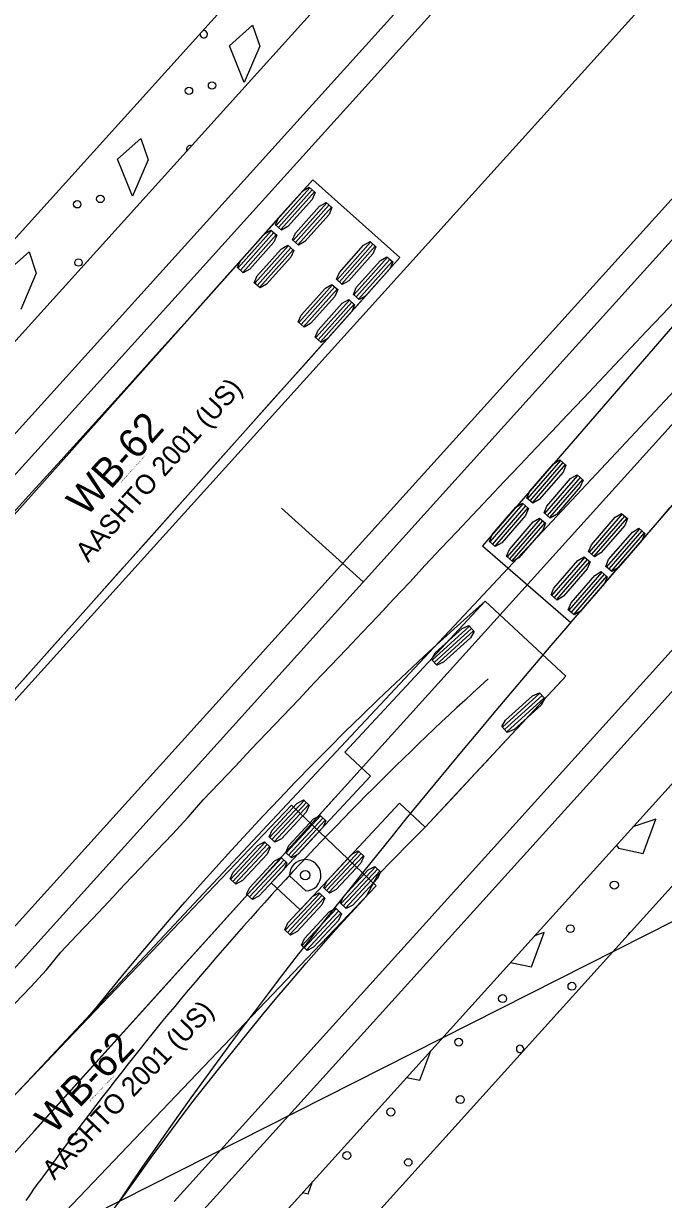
# Model space of a CAD drawing. Extents: x 1262642 to 1268358, y 767825 to 773481.
# Drawn here: x 1266867.8 to 1266914.3, y 772243.3 to 772328.8 of the extents above; entities that cross this region are included whole.
import ezdxf

# ---------------------------------------------------------------- set-up
doc = ezdxf.new("R2010")
doc.units = 0
for name, color, linetype in [('Prop Conc 2ft 6in Curb and Gutter', 7, 'Continuous'), ('Prop Conc 4in Sidewalk', 7, 'Continuous'), ('Prop Dimension Text', 7, 'Continuous'), ('Prop EOT', 7, 'Continuous'), ('Prop Horizontal Alignment', 7, 'Continuous'), ('Prop Horizontal Alignment Tick Large', 7, 'Continuous'), ('Prop Lane Lines', 7, 'Continuous'), ('Scratch_Level_3', 7, 'Continuous')]:
    doc.layers.add(name, color=color, linetype=linetype)

msp = doc.modelspace()

# ---------------------------------------------------------------- linework, layer by layer
at = {"layer": 'Prop Conc 2ft 6in Curb and Gutter'}
for p, q in [((1267131.944, 772606.254), (1266835.453, 772278.077)), ((1267135.454, 772602.68), (1266839.163, 772274.725)), ((1267138.613, 772599.464), (1266842.502, 772271.708)), ((1267174.15, 772567.197), (1266880.184, 772241.815)), ((1266883.523, 772238.798), (1267177.489, 772564.181)), ((1267181.289, 772560.929), (1266887.233, 772235.447)), ((1266882.725, 772327.166), (1266884.411, 772328.663)), ((1266884.411, 772328.663), (1266884.935, 772327.129)), ((1266883.805, 772324.487), (1266882.725, 772327.166)), ((1266884.935, 772327.129), (1266883.805, 772324.487)), ((1266874.601, 772318.921), (1266876.287, 772320.419)), ((1266876.287, 772320.419), (1266876.811, 772318.885)), ((1266875.682, 772316.242), (1266874.601, 772318.921)), ((1266876.811, 772318.885), (1266875.682, 772316.242)), ((1266866.478, 772310.677), (1266868.164, 772312.174)), ((1266868.164, 772312.174), (1266868.688, 772310.64)), ((1266868.688, 772310.64), (1266867.559, 772307.998)), ((1266913.737, 772270.958), (1266912.067, 772270.393)), ((1266912.818, 772268.458), (1266913.737, 772270.958)), ((1266910.864, 772269.061), (1266911.012, 772268.834)), ((1266911.012, 772268.834), (1266912.818, 772268.458)), ((1266904.695, 772260.214), (1266905.614, 772262.713)), ((1266905.614, 772262.713), (1266904.916, 772262.478)), ((1266903.159, 772260.533), (1266904.695, 772260.214)), ((1266896.572, 772251.97), (1266897.36, 772254.115)), ((1266895.604, 772252.171), (1266896.572, 772251.97)), ((1266888.449, 772243.725), (1266888.774, 772244.611)), ((1266888.049, 772243.808), (1266888.449, 772243.725))]:
    msp.add_line(p, q, dxfattribs=at)
for centre, radius in [((1266879.787, 772323.887), 0.268), ((1266881.464, 772324.276), 0.268), ((1266873.341, 772316.031), 0.268), ((1266871.664, 772315.642), 0.268), ((1266871.754, 772311.404), 0.268), ((1266910.712, 772266.151), 0.292), ((1266907.515, 772262.984), 0.285), ((1266907.633, 772258.804), 0.289), ((1266902.589, 772257.906), 0.292), ((1266899.392, 772254.74), 0.285), ((1266899.51, 772250.56), 0.289), ((1266894.466, 772249.662), 0.292), ((1266891.268, 772246.495), 0.285), ((1266895.732, 772246.001), 0.268)]:
    msp.add_circle(centre, radius, dxfattribs=at)
for centre, start, end in [((1266880.863, 772327.995), 168.70007, 107.10757), ((1266879.877, 772319.648), 68.58721, 207.22043), ((1266911.979, 772262.49), 108.17506, 167.63259), ((1266903.856, 772254.245), 112.12802, 313.44003), ((1266903.856, 772254.245), 322.36762, 112.12802)]:
    msp.add_arc(centre, 0.268, start, end, dxfattribs=at)
at = {"layer": 'Prop Conc 4in Sidewalk'}
for p, q in [((1267131.944, 772606.254), (1266835.453, 772278.077)), ((1267135.454, 772602.68), (1266839.163, 772274.725)), ((1267177.489, 772564.181), (1266883.523, 772238.798)), ((1267181.199, 772560.829), (1266887.233, 772235.447))]:
    msp.add_line(p, q, dxfattribs=at)
at = {"layer": 'Prop Dimension Text'}
msp.add_lwpolyline([(1266927.819, 772269.993), (1266826.047, 772218.568)], dxfattribs=at)
at = {"layer": 'Prop EOT'}
for p, q in [((1267140.017, 772598.035), (1266843.986, 772270.367)), ((1267172.665, 772568.538), (1266878.7, 772243.156))]:
    msp.add_line(p, q, dxfattribs=at)
at = {"layer": 'Prop Horizontal Alignment'}
msp.add_line((1266770.936, 772153.71), (1267443.049, 772897.651), dxfattribs=at)
msp.add_arc((1275047.307, 780021.225), 11400, 222.9935866, 225.4043192, dxfattribs=at)
at = {"layer": 'Prop Horizontal Alignment Tick Large'}
msp.add_line((1266892.443, 772288.202), (1266886.507, 772293.565), dxfattribs=at)
at = {"layer": 'Prop Lane Lines'}
for p, q in [((1267148.179, 772590.66), (1266852.149, 772262.993)), ((1267156.341, 772583.286), (1266860.311, 772255.619)), ((1267164.503, 772575.912), (1266868.473, 772248.245)), ((1266890.345, 772272.454), (1266862.92, 772242.098))]:
    msp.add_line(p, q, dxfattribs=at)
at = {"layer": 'Scratch_Level_3'}
for p, q in [((1266841.285, 772223.318), (1266947.116, 772336.274)), ((1266932.537, 772327.091), (1266901.116, 772290.805)), ((1266907.541, 772285.241), (1266938.963, 772321.527)), ((1266888.785, 772317.431), (1266856.816, 772281.626)), ((1266895.125, 772311.77), (1266888.785, 772317.431)), ((1266886.125, 772314.108), (1266888.567, 772316.843)), ((1266886.296, 772313.955), (1266888.738, 772316.69)), ((1266886.467, 772313.803), (1266888.909, 772316.538)), ((1266887.356, 772313.009), (1266889.798, 772315.744)), ((1266887.527, 772312.856), (1266889.969, 772315.591)), ((1266887.698, 772312.704), (1266890.14, 772315.439)), ((1266883.35, 772311), (1266885.792, 772313.735)), ((1266883.521, 772310.847), (1266885.963, 772313.582)), ((1266883.692, 772310.695), (1266886.134, 772313.43)), ((1266884.581, 772309.901), (1266887.023, 772312.636)), ((1266890.551, 772310.156), (1266892.993, 772312.891)), ((1266890.722, 772310.004), (1266893.164, 772312.739)), ((1266863.156, 772275.965), (1266895.125, 772311.77)), ((1266884.752, 772309.748), (1266887.194, 772312.483)), ((1266884.923, 772309.596), (1266887.365, 772312.331)), ((1266890.893, 772309.851), (1266893.335, 772312.586)), ((1266891.782, 772309.057), (1266894.224, 772311.792)), ((1266891.953, 772308.905), (1266894.395, 772311.64)), ((1266892.124, 772308.752), (1266894.566, 772311.487)), ((1266887.776, 772307.048), (1266890.218, 772309.783)), ((1266887.947, 772306.896), (1266890.389, 772309.631)), ((1266888.118, 772306.743), (1266890.56, 772309.478)), ((1266889.007, 772305.949), (1266891.449, 772308.684)), ((1266889.178, 772305.797), (1266891.62, 772308.532)), ((1266889.349, 772305.644), (1266891.791, 772308.379)), ((1266906.799, 772297.018), (1266904.398, 772294.246)), ((1266906.972, 772296.868), (1266904.572, 772294.096)), ((1266907.145, 772296.718), (1266904.745, 772293.946)), ((1266908.046, 772295.938), (1266905.646, 772293.166)), ((1266908.219, 772295.788), (1266905.819, 772293.016)), ((1266908.392, 772295.638), (1266905.992, 772292.866)), ((1266904.071, 772293.868), (1266901.671, 772291.096)), ((1266904.244, 772293.718), (1266901.844, 772290.946)), ((1266904.417, 772293.568), (1266902.017, 772290.796)), ((1266911.284, 772293.134), (1266908.884, 772290.362)), ((1266911.457, 772292.984), (1266909.057, 772290.212)), ((1266905.318, 772292.788), (1266902.918, 772290.016)), ((1266905.492, 772292.638), (1266903.091, 772289.866)), ((1266905.665, 772292.488), (1266903.265, 772289.716)), ((1266911.63, 772292.834), (1266909.23, 772290.062)), ((1266912.531, 772292.054), (1266910.131, 772289.282)), ((1266912.704, 772291.904), (1266910.304, 772289.132)), ((1266912.878, 772291.754), (1266910.477, 772288.982)), ((1266901.116, 772290.805), (1266907.541, 772285.241)), ((1266908.556, 772289.984), (1266906.156, 772287.212)), ((1266908.73, 772289.834), (1266906.329, 772287.062)), ((1266908.903, 772289.684), (1266906.503, 772286.912)), ((1266909.804, 772288.904), (1266907.403, 772286.132)), ((1266909.977, 772288.754), (1266907.577, 772285.982)), ((1266910.15, 772288.604), (1266907.75, 772285.832)), ((1266901.331, 772286.791), (1266891.108, 772275.814)), ((1266907.186, 772281.339), (1266901.331, 772286.791)), ((1266901.331, 772286.791), (1266901.331, 772286.791)), ((1266900.172, 772284.98), (1266897.457, 772282.516)), ((1266900.326, 772284.811), (1266897.611, 772282.346)), ((1266900.48, 772284.641), (1266897.765, 772282.177)), ((1266896.963, 772270.362), (1266907.186, 772281.339)), ((1266905.303, 772280.095), (1266902.582, 772277.637)), ((1266905.456, 772279.925), (1266902.736, 772277.467)), ((1266905.61, 772279.755), (1266902.889, 772277.297)), ((1266891.108, 772275.814), (1266892.987, 772274.065)), ((1266892.987, 772274.065), (1266885.774, 772266.32)), ((1266887.239, 772271.972), (1266854.098, 772237.25)), ((1266888.152, 772272.304), (1266885.653, 772269.621)), ((1266888.32, 772272.148), (1266885.821, 772269.465)), ((1266888.488, 772271.992), (1266885.989, 772269.308)), ((1266893.388, 772266.104), (1266887.239, 772271.972)), ((1266887.239, 772271.972), (1266887.239, 772271.972)), ((1266887.871, 772264.366), (1266895.084, 772272.111)), ((1266895.084, 772272.111), (1266896.963, 772270.362)), ((1266889.36, 772271.179), (1266886.861, 772268.496)), ((1266889.528, 772271.023), (1266887.029, 772268.34)), ((1266889.695, 772270.867), (1266887.196, 772268.184)), ((1266885.313, 772269.255), (1266882.814, 772266.572)), ((1266885.48, 772269.099), (1266882.981, 772266.415)), ((1266885.648, 772268.943), (1266883.149, 772266.259)), ((1266892.128, 772268.601), (1266889.629, 772265.918)), ((1266892.296, 772268.445), (1266889.797, 772265.762)), ((1266892.464, 772268.289), (1266889.965, 772265.605)), ((1266886.52, 772268.13), (1266884.021, 772265.447)), ((1266886.688, 772267.974), (1266884.189, 772265.291)), ((1266886.855, 772267.818), (1266884.357, 772265.135)), ((1266893.336, 772267.476), (1266890.837, 772264.793)), ((1266893.504, 772267.32), (1266891.005, 772264.637)), ((1266887.1, 772266.827), (1266888.283, 772265.726)), ((1266893.671, 772267.164), (1266891.172, 772264.481)), ((1266860.247, 772231.381), (1266893.388, 772266.104)), ((1266885.774, 772266.32), (1266887.871, 772264.366)), ((1266889.289, 772265.552), (1266886.79, 772262.869)), ((1266889.456, 772265.396), (1266886.957, 772262.712)), ((1266889.624, 772265.239), (1266887.125, 772262.556)), ((1266890.496, 772264.427), (1266887.997, 772261.744)), ((1266890.664, 772264.271), (1266888.165, 772261.588)), ((1266890.832, 772264.115), (1266888.333, 772261.432))]:
    msp.add_line(p, q, dxfattribs=at)
for points in [[(1266888.785, 772317.431), (1266886.501, 772314.873), (1266884.218, 772312.316), (1266881.934, 772309.759), (1266879.648, 772307.204), (1266877.359, 772304.651), (1266875.066, 772302.102), (1266872.768, 772299.557), (1266870.464, 772297.018), (1266868.154, 772294.484), (1266865.837, 772291.958)], [(1266895.125, 772311.77), (1266892.842, 772309.212), (1266890.559, 772306.654), (1266888.276, 772304.096), (1266885.991, 772301.54), (1266883.708, 772298.982), (1266881.424, 772296.425), (1266879.141, 772293.867), (1266876.857, 772291.31), (1266874.574, 772288.752), (1266872.29, 772286.195), (1266870.007, 772283.637), (1266867.723, 772281.08)], [(1266867.125, 772257.538), (1266868.277, 772258.771), (1266869.43, 772260.003), (1266870.482, 772261.278), (1266871.639, 772262.507), (1266872.796, 772263.735), (1266873.953, 772264.962), (1266875.111, 772266.188), (1266876.267, 772267.413), (1266877.424, 772268.637), (1266878.581, 772269.86), (1266879.737, 772271.083), (1266880.822, 772272.343), (1266881.981, 772273.564), (1266883.138, 772274.783), (1266884.296, 772276.002), (1266885.453, 772277.221), (1266886.609, 772278.439), (1266887.765, 772279.656), (1266888.92, 772280.873), (1266890.075, 772282.09), (1266891.229, 772283.307), (1266892.383, 772284.523), (1266893.536, 772285.739), (1266894.689, 772286.954), (1266895.841, 772288.17), (1266896.954, 772289.412), (1266898.107, 772290.627), (1266899.259, 772291.841), (1266900.411, 772293.055), (1266901.563, 772294.269), (1266902.714, 772295.483), (1266903.864, 772296.697), (1266905.015, 772297.911), (1266906.164, 772299.125), (1266907.314, 772300.339), (1266908.463, 772301.554), (1266909.612, 772302.768), (1266910.76, 772303.982), (1266911.908, 772305.196), (1266913.056, 772306.41), (1266914.203, 772307.624), (1266915.35, 772308.838)], [(1266874.748, 772243.211), (1266875.582, 772244.447), (1266876.431, 772245.688), (1266877.293, 772246.934), (1266878.169, 772248.185), (1266879.056, 772249.439), (1266879.956, 772250.696), (1266880.867, 772251.955), (1266881.788, 772253.217), (1266882.72, 772254.481), (1266883.662, 772255.746), (1266884.613, 772257.013), (1266885.574, 772258.28), (1266886.542, 772259.549), (1266887.519, 772260.817), (1266888.504, 772262.086), (1266889.496, 772263.355), (1266890.495, 772264.623), (1266891.501, 772265.892), (1266892.513, 772267.16), (1266893.531, 772268.427), (1266894.554, 772269.694), (1266895.584, 772270.96), (1266896.618, 772272.225), (1266897.658, 772273.49), (1266898.702, 772274.754), (1266899.75, 772276.016), (1266900.803, 772277.278), (1266901.86, 772278.539), (1266902.921, 772279.799), (1266903.985, 772281.057), (1266905.053, 772282.315), (1266906.124, 772283.572), (1266907.199, 772284.827), (1266908.276, 772286.082), (1266909.356, 772287.335), (1266910.439, 772288.588), (1266911.524, 772289.84), (1266912.609, 772291.093), (1266913.694, 772292.346), (1266914.78, 772293.601)], [(1266867.148, 772250.922), (1266868.31, 772252.139), (1266869.474, 772253.359), (1266870.64, 772254.581), (1266871.808, 772255.804), (1266872.924, 772257.081), (1266873.992, 772258.404), (1266875.07, 772259.719), (1266876.157, 772261.027), (1266877.254, 772262.326), (1266878.36, 772263.618), (1266879.476, 772264.902), (1266880.6, 772266.178), (1266881.734, 772267.445), (1266882.877, 772268.705), (1266884.03, 772269.956), (1266885.191, 772271.198), (1266886.361, 772272.433), (1266887.54, 772273.659), (1266888.727, 772274.876), (1266889.924, 772276.085), (1266891.129, 772277.285), (1266892.343, 772278.476), (1266893.565, 772279.659), (1266894.796, 772280.832), (1266896.036, 772281.997), (1266897.283, 772283.153), (1266898.539, 772284.3), (1266899.804, 772285.438), (1266901.076, 772286.566), (1266901.331, 772286.791)], [(1266874.129, 772242.351), (1266875.132, 772243.662), (1266876.086, 772245.013), (1266877.049, 772246.353), (1266878.022, 772247.684), (1266879.005, 772249.005), (1266879.998, 772250.317), (1266881.001, 772251.619), (1266882.041, 772252.885), (1266883.062, 772254.172), (1266884.092, 772255.45), (1266885.132, 772256.719), (1266886.181, 772257.979), (1266887.241, 772259.23), (1266888.31, 772260.472), (1266889.388, 772261.705), (1266890.476, 772262.928), (1266891.58, 772264.137), (1266892.684, 772265.345), (1266893.485, 772266.842), (1266894.624, 772268.017), (1266895.771, 772269.183), (1266896.926, 772270.342), (1266898.05, 772271.529), (1266899.164, 772272.725), (1266900.278, 772273.922), (1266901.392, 772275.118), (1266902.506, 772276.314), (1266903.62, 772277.511), (1266904.735, 772278.707), (1266905.849, 772279.903), (1266906.963, 772281.099), (1266907.186, 772281.339)], [(1266867.955, 772243.224), (1266868.141, 772243.5), (1266868.329, 772243.775), (1266868.519, 772244.049), (1266868.711, 772244.322), (1266868.905, 772244.593)]]:
    msp.add_lwpolyline(points, dxfattribs=at)
for points in [[(1266886.509, 772313.765), (1266886.083, 772314.146), (1266886.296, 772314.643), (1266888.054, 772316.613), (1266888.525, 772316.881), (1266888.951, 772316.5), (1266888.738, 772316.002), (1266886.98, 772314.033)], [(1266887.74, 772312.666), (1266887.313, 772313.047), (1266887.527, 772313.545), (1266889.285, 772315.514), (1266889.756, 772315.782), (1266890.182, 772315.401), (1266889.969, 772314.903), (1266888.211, 772312.934)], [(1266883.734, 772310.657), (1266883.308, 772311.038), (1266883.521, 772311.535), (1266885.279, 772313.505), (1266885.75, 772313.773), (1266886.176, 772313.392), (1266885.963, 772312.894), (1266884.205, 772310.925)], [(1266884.965, 772309.558), (1266884.538, 772309.939), (1266884.752, 772310.436), (1266886.51, 772312.406), (1266886.98, 772312.674), (1266887.407, 772312.293), (1266887.194, 772311.795), (1266885.435, 772309.826)], [(1266890.935, 772309.813), (1266890.509, 772310.194), (1266890.722, 772310.692), (1266892.48, 772312.661), (1266892.951, 772312.929), (1266893.377, 772312.548), (1266893.164, 772312.051), (1266891.406, 772310.081)], [(1266892.166, 772308.714), (1266891.739, 772309.095), (1266891.953, 772309.593), (1266893.711, 772311.562), (1266894.181, 772311.83), (1266894.608, 772311.449), (1266894.395, 772310.952), (1266892.636, 772308.982)], [(1266888.16, 772306.705), (1266887.733, 772307.086), (1266887.947, 772307.584), (1266889.705, 772309.553), (1266890.176, 772309.821), (1266890.602, 772309.44), (1266890.389, 772308.942), (1266888.631, 772306.973)], [(1266889.391, 772305.606), (1266888.964, 772305.987), (1266889.178, 772306.485), (1266890.936, 772308.454), (1266891.406, 772308.722), (1266891.833, 772308.341), (1266891.62, 772307.844), (1266889.861, 772305.874)], [(1266906.756, 772297.055), (1266907.188, 772296.681), (1266906.982, 772296.18), (1266905.254, 772294.184), (1266904.788, 772293.909), (1266904.355, 772294.283), (1266904.561, 772294.784), (1266906.289, 772296.78)], [(1266908.003, 772295.975), (1266908.435, 772295.6), (1266908.23, 772295.1), (1266906.501, 772293.104), (1266906.035, 772292.829), (1266905.603, 772293.203), (1266905.808, 772293.704), (1266907.537, 772295.7)], [(1266904.028, 772293.905), (1266904.46, 772293.531), (1266904.255, 772293.03), (1266902.526, 772291.034), (1266902.06, 772290.759), (1266901.628, 772291.133), (1266901.834, 772291.634), (1266903.562, 772293.63)], [(1266911.241, 772293.171), (1266911.673, 772292.796), (1266911.468, 772292.296), (1266909.739, 772290.3), (1266909.273, 772290.025), (1266908.841, 772290.399), (1266909.046, 772290.9), (1266910.775, 772292.896)], [(1266905.275, 772292.825), (1266905.708, 772292.451), (1266905.502, 772291.95), (1266903.774, 772289.954), (1266903.307, 772289.679), (1266902.875, 772290.053), (1266903.081, 772290.554), (1266904.809, 772292.55)], [(1266912.488, 772292.091), (1266912.921, 772291.716), (1266912.715, 772291.215), (1266910.987, 772289.22), (1266910.52, 772288.945), (1266910.088, 772289.319), (1266910.294, 772289.82), (1266912.022, 772291.816)], [(1266908.513, 772290.021), (1266908.946, 772289.647), (1266908.74, 772289.146), (1266907.012, 772287.15), (1266906.546, 772286.875), (1266906.113, 772287.249), (1266906.319, 772287.75), (1266908.047, 772289.746)], [(1266909.761, 772288.941), (1266910.193, 772288.567), (1266909.987, 772288.066), (1266908.259, 772286.07), (1266907.793, 772285.795), (1266907.36, 772286.169), (1266907.566, 772286.67), (1266909.294, 772288.666)], [(1266900.133, 772285.022), (1266900.518, 772284.599), (1266900.253, 772284.126), (1266898.299, 772282.352), (1266897.803, 772282.134), (1266897.418, 772282.558), (1266897.683, 772283.031), (1266899.637, 772284.805)], [(1266905.265, 772280.138), (1266905.648, 772279.713), (1266905.383, 772279.241), (1266903.424, 772277.471), (1266902.928, 772277.255), (1266902.544, 772277.679), (1266902.809, 772278.151), (1266904.768, 772279.921)], [(1266888.111, 772272.343), (1266888.529, 772271.953), (1266888.306, 772271.46), (1266886.506, 772269.528), (1266886.03, 772269.27), (1266885.612, 772269.66), (1266885.836, 772270.153), (1266887.635, 772272.085)], [(1266889.318, 772271.218), (1266889.737, 772270.828), (1266889.513, 772270.335), (1266887.714, 772268.403), (1266887.238, 772268.145), (1266886.819, 772268.535), (1266887.043, 772269.028), (1266888.842, 772270.96)], [(1266885.271, 772269.294), (1266885.69, 772268.904), (1266885.466, 772268.411), (1266883.667, 772266.479), (1266883.191, 772266.221), (1266882.772, 772266.61), (1266882.996, 772267.104), (1266884.795, 772269.035)], [(1266886.479, 772268.169), (1266886.897, 772267.779), (1266886.673, 772267.286), (1266884.874, 772265.354), (1266884.398, 772265.096), (1266883.98, 772265.486), (1266884.203, 772265.979), (1266886.003, 772267.911)], [(1266892.087, 772268.64), (1266892.505, 772268.25), (1266892.282, 772267.757), (1266890.482, 772265.825), (1266890.006, 772265.567), (1266889.588, 772265.956), (1266889.812, 772266.45), (1266891.611, 772268.381)], [(1266893.294, 772267.515), (1266893.713, 772267.125), (1266893.489, 772266.632), (1266891.69, 772264.7), (1266891.214, 772264.442), (1266890.795, 772264.832), (1266891.019, 772265.325), (1266892.818, 772267.257)], [(1266889.247, 772265.591), (1266889.666, 772265.201), (1266889.442, 772264.708), (1266887.643, 772262.776), (1266887.167, 772262.518), (1266886.748, 772262.907), (1266886.972, 772263.4), (1266888.771, 772265.332)], [(1266890.455, 772264.466), (1266890.873, 772264.076), (1266890.649, 772263.583), (1266888.85, 772261.651), (1266888.374, 772261.393), (1266887.956, 772261.783), (1266888.179, 772262.276), (1266889.979, 772264.208)]]:
    msp.add_lwpolyline(points, close=True, dxfattribs=at)
msp.add_circle((1266888.242, 772266.868), 0.34, dxfattribs=at)
for centre, radius, start, end in [((1267056.919, 772109.572), 231.473, 132.16704, 144.31627), ((1266888.242, 772266.868), 1.143, 272.03613, 182.03613)]:
    msp.add_arc(centre, radius, start, end, dxfattribs=at)

# ---------------------------------------------------------------- texts
for s, height, rotation, p in [('AASHTO 2001 (US)', 1.41667, 48.23946, (1266872.456, 772289.56)), ('WB-62', 2.125, 48.23946, (1266872.305, 772292.848)), ('(c) 2016 Transoft Solutions, Inc. All rights reserved.', 0.085, 48.23946, (1266874.848, 772295.377)), ('AASHTO 2001 (US)', 1.41667, 46.33529, (1266869.993, 772244.66)), ('WB-62', 2.125, 46.33529, (1266869.952, 772247.951)), ('(c) 2016 Transoft Solutions, Inc. All rights reserved.', 0.085, 46.33529, (1266872.578, 772250.394))]:
    msp.add_text(s, height=height, rotation=rotation, dxfattribs=at).set_placement(p)

doc.saveas('drawing.dxf')
